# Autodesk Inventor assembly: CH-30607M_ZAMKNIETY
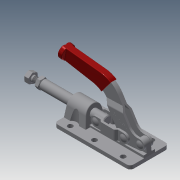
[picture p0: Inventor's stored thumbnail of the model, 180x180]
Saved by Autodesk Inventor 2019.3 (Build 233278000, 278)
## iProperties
Company: Î¢ÈíÖÐ¹ú
Created: 2012-09
Part Number: CH-30607M_ZAMKNIETY
Material: Ogólny
Description: STEP AP203
Document SubType Name: Assembly
Designer: CADENGINEERING4
Sending System: SolidWorks 2010
Preprocessor: SwSTEP 2.0
Title: CH-30607M.STEP
Author: Î¢ÈíÓÃ»§
Revision Number: ÈÎºÎ
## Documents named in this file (10)
- D:\Vault_2016\Projekty\STRONA\Push-pull clamp\CH-30607M\CH-30607M_ZAMKNIETY.iam
- D:\Vault_2016\Projekty\STRONA\Push-pull clamp\CH-30607M\CH-30607-01 BASE.ipt
- D:\Vault_2016\Projekty\STRONA\Push-pull clamp\CH-30607M\M8 Nut.ipt
- D:\Vault_2016\Projekty\STRONA\Push-pull clamp\CH-30607M\CH-SA-085012 SPINDLE SUPPLIED.ipt
- D:\Vault_2016\Projekty\STRONA\Push-pull clamp\CH-30607M\CH-30607-07.ipt
- D:\Vault_2016\Projekty\STRONA\Push-pull clamp\CH-30607M\CH-30607-05.ipt
- D:\Vault_2016\Projekty\STRONA\Push-pull clamp\CH-30607M\CH-30607-04 CONNECTING-PLATE.ipt
- D:\Vault_2016\Projekty\STRONA\Push-pull clamp\CH-30607M\CH-30607-06.ipt
- D:\Vault_2016\Projekty\STRONA\Push-pull clamp\CH-30607M\CH-30607-03 HANDLE.ipt
- D:\Vault_2016\Projekty\STRONA\Push-pull clamp\CH-30607M\CH-30607-02 CREST STALK.ipt
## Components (11 placed, 11 different names)
1. CH-30607-01 BASE_1
2. M8 Nut_2
3. CH-SA-085012 SPINDLE SUPPLIED_3
4. CH-30607-07_4
5. CH-30607-05_5
6. CH-30607-04 CONNECTING-PLATE_6
7. CH-30607-07_7
8. CH-30607-06_8
9. CH-30607-04 CONNECTING-PLATE_9
10. CH-30607-03 HANDLE_10
11. CH-30607-02 CREST STALK_11
